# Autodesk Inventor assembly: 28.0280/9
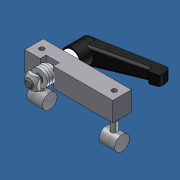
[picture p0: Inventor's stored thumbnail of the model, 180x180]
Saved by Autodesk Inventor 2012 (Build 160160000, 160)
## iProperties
Created: 2015-03
Part Number: 28.0280/9
Document SubType Name: Assembly
Designer: Admin
Description: SLIDE CLAMPING UNIT FOR SLIDE LWN-S
Vendor: S
Author: Admin
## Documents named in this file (3)
- C:\Andys Backup Data\ANDY'S INVENTOR\INVENTOR LIBRARIES\PARTS LIBRARY\READY FOR USE MODULES LG\28.0280_9 SLIDE CLAMPING UNIT FOR SLIDE LWN-S.iam
- C:\Andys Backup Data\ANDY'S INVENTOR\INVENTOR LIBRARIES\PARTS LIBRARY\READY FOR USE MODULES LG\SUBCOMPONENTS\28.0280 SLIDE CLAMPING UNIT FOR SLIDE LWN-S.iam
- C:\Andys Backup Data\ANDY'S INVENTOR\INVENTOR LIBRARIES\PARTS LIBRARY\FASTENING ELEMENTS\SET SCREWS\21.9841 M4X5 FLAT POINT DIN 913.ipt
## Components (2 placed, 2 different names)
1. 28.0280 SLIDE CLAMPING UNIT FOR SLIDE LWN-S:1 [sub-assembly] — Mate:1, Tangent:1
2. 21.9841 SET SCREW M4X5 FLAT POINT DIN 913:1 — Mate:1, Tangent:1
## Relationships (2: Mate 1, Tangent 1)
- Mate:1: 28.0280 SLIDE CLAMPING UNIT FOR SLIDE LWN-S:1 ↔ 21.9841 SET SCREW M4X5 FLAT POINT DIN 913:1
- Tangent:1: 28.0280 SLIDE CLAMPING UNIT FOR SLIDE LWN-S:1 ↔ 21.9841 SET SCREW M4X5 FLAT POINT DIN 913:1
